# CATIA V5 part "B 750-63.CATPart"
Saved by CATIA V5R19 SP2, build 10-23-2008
Part number: B 750-63
Bounding box of the stored display mesh (mm): x -22.494 to 22.494, y -22.494 to 22.494, z 0 to 212
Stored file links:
  C:\Users\Bora\Desktop\3D Katı model\B serisi\B 750\B 750-63.CATPart
  C:\Program Files\Dassault Systemes\B19\intel_a\reffiles\standard\MetricThickPitch.txt
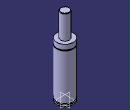
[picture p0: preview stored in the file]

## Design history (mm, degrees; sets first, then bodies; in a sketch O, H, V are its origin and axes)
Body1 (main body)
  Sketch1 on yz-plane, origin (0, 0, 0), H (0, 1, 0), V (0, 0, 1)
    point P3 (12, 211)
    point P5 (12, 211)
    point P7 (22.5, 133.5)
    point P8 (22.5, 131.5)
    point P12 (22.5, 131.5)
    point P13 (22.5, 133.5)
    line L1 (22.5, 0) -> (22.5, 4)
    line L2 (12, 211) -> (12, 147)
    arc A1 centre (11, 211) radius 1 from (12, 211) to (11, 212) ccw
    arc A2 centre (22.5, 132.5) radius 1 from (22.5, 133.5) to (22.5, 131.5) ccw
    line L3 (20, 7.5) -> (20, 4)
    line L4 (22.5, 7.5) -> (22.5, 131.5)
    line L5 (22.5, 133.5) -> (22.5, 147)
    line L6 (11, 212) -> (0, 212)
    point P15 (0, 212)
    line L7 (12, 147) -> (22.5, 147)
    line L8 (0, 0) -> (22.5, 0)
    line L9 (20, 7.5) -> (22.5, 7.5)
    line L10 (20, 4) -> (22.5, 4)
    coincidence: P15 V, P3 P5, P7 P13, P8 P12
    tangency: L6 A1
    horizontal: L7 H, L8 H, L9 H, L10 H
  Shaft1: profile Sketch1, axis Sketch1.V, angle 360
  Sketch2 on face of Shaft1 from Sketch1.L8, origin (0, 0, 0), H (1, 0, 0), V (0, -1, 0)
    point P1 (10, 0)
    distance P1 V = 10
  Hole1: placed by Sketch2, at (10, 0, 0) direction (0, 0, 1), diameter 6.647, depth 13, threaded "M8", thread diameter 8, thread depth 13, pitch 1.25
  CircPattern1: of Hole1, instances 2, angular step 180, axis from xy-plane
